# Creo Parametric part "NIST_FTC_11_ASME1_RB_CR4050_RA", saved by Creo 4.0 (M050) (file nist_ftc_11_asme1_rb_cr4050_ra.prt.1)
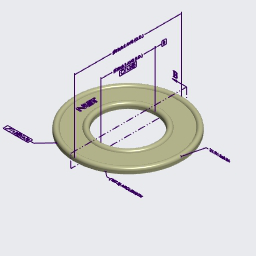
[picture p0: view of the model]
Units: millimeter Kilogram Sec (mmKs); MM, KILOGRAM, SECS

Other parameters: OUTSIDE_CIRCLE_ARCLENGTH

Created from: NIST_FTC_11_CREO4M050_STEP_GEOM.PRT

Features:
  1. datum plane "RIGHT"
  2. datum plane "TOP"
  3. datum plane "FRONT"
  4. coordinate system
  5. imported feature
  6. annotation "Annotation 1"
  7. sketch "Sketch 1"
  8. annotation "Annotation 2"
  9. sketch "Sketch 2"

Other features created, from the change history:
  planar section "XSEC0001"

Other named items: AD3, AD6, GP0, DATUM_TAG_B, GP1, DATUM_TAG_A, GP2, DRF1, AD8, AE_NOTE0, GP3, AD15, AD16, AE_SYMBOL0, MBD_A, MBD_B, ANNOT_LAYER_STATE0001, ANNOT_LAYER_STATE0002

Layers: ALL_ANNOTATIONS, ALL_AXES, ALL_CSYS, ALL_CURVES, ALL_PLANES, ALL_POINTS, ALL_QUILTS, DEF_CSYS, DEF_PLANES

Notes: NOTES (UNLESS OTHERWISE SPECIFIED): | 1.  CAD MODEL ___________ REV. __ IS |      REQUIRED TO COMPLETE PRODUCT |      DEFINITION. | 2.  DIRECTLY-TOLERANCED DIMENSIONS |      AND BASIC DIMENSIONS DEFINED ON |      THE DRAWING TAKE PRECEDENCE OVER |      DIMENSIONAL DATA DEFINED BY THE |      MODEL. OBTAIN ALL OTHER |      DIMENSIONAL DATA FROM THE MODEL. |      THE MODEL REPRESENTS BASIC |      DIMENSIONAL DATA UNLESS OTHERWISE |      SPECIFIED. | 3.  APPLICABLE STANDARDS: |      ASME Y14.41-2003 APPLIES TO DATASET. |      ASME Y14.5M-1994 APPLIES TO |      DIMENSIONING AND TOLERANCING. | 4.  NON-RIGID PART. DIRECTLYTOLERANCED |      DIMENSIONS AND |      TOLERANCES APPLY IN FREE STATE. | 5.  UNITS: MILLIMETERS | �⌖ | 0.01 | �⏥ | 0.3Ⓕ | �⌓ | 0.3Ⓕ | A | B | 2X R0.1 MAX | �↗ | 1.2Ⓕ | A | B | 197.9 | ) ARCLENGTH

Surfaces: 8 torus, 4 cylinder, 2 plane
